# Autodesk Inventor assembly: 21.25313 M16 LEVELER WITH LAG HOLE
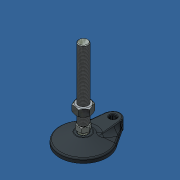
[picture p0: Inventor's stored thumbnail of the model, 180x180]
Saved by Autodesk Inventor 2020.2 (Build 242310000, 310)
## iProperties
Created: 2015-09
Part Number: 21.25313 M16 LEVELER WITH LAG HOLE
Description: Gelenkfuß M16 D 80 mit einer Befestigungsbohrung
Document SubType Name: Assembly
Designer: MuellerJ
Mass: 322.747 g
Surface Area: 402.798 cm^2
Volume: 97.546 cm^3
Density: 3.30867 g/cm^3
Beschreibung: Gelenkfuß M16 D 80 mit einer Befestigungsbohrung
Bezeichnung: Gelenkfuß M16 D 80 mit einer Befestigungsbohrung
Artikelnr: 212513/0
AIMD_ORIGIN: 00202212
Lieferantennr: 72401
Zeichnungsnr: leer
MiniTec_ID: 212513/0
Teileart: BK
Lieferant: MiniTec
Title: Gelenkfuß M16 D 80 mit einer Befestigungsbohrung
Author: MuellerJ
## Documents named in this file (5)
- Y:\INVENTOR LIBRARIES\PARTS LIBRARY\FEET WHEELS FLOOR FASTENING SUPPORTS\21.2513 M16 LEVELER WITH LAG HOLE.iam
- Y:\INVENTOR LIBRARIES\PARTS LIBRARY\FEET WHEELS FLOOR FASTENING SUPPORTS\SUBCOMPONENTS\LEVELING FEET SUBCOMPONENTS\21.2513 M16 STUD.ipt
- Y:\INVENTOR LIBRARIES\PARTS LIBRARY\FEET WHEELS FLOOR FASTENING SUPPORTS\SUBCOMPONENTS\LEVELING FEET SUBCOMPONENTS\21.2510 PLASTIC PAD.ipt
- Y:\INVENTOR LIBRARIES\PARTS LIBRARY\FEET WHEELS FLOOR FASTENING SUPPORTS\SUBCOMPONENTS\LEVELING FEET SUBCOMPONENTS\21.2510 RUBBER PAD.ipt
- Y:\INVENTOR LIBRARIES\PARTS LIBRARY\FASTENING ELEMENTS\NUTS\21.1529 M16 HEX NUT.ipt
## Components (4 placed, 4 different names)
1. PLASTIC PAD WITH LAG HOLE — Passend:2, Passend:3, Passend:4
2. RUBBER PAD — Passend:2, Passend:3, Passend:4
3. M16 THREADED STUD
4. M16 HEX NUT
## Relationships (3: Mate 3)
- Passend:2 [Mate]: PLASTIC PAD WITH LAG HOLE ↔ RUBBER PAD
- Passend:3 [Mate]: PLASTIC PAD WITH LAG HOLE ↔ RUBBER PAD
- Passend:4 [Mate]: PLASTIC PAD WITH LAG HOLE ↔ RUBBER PAD
